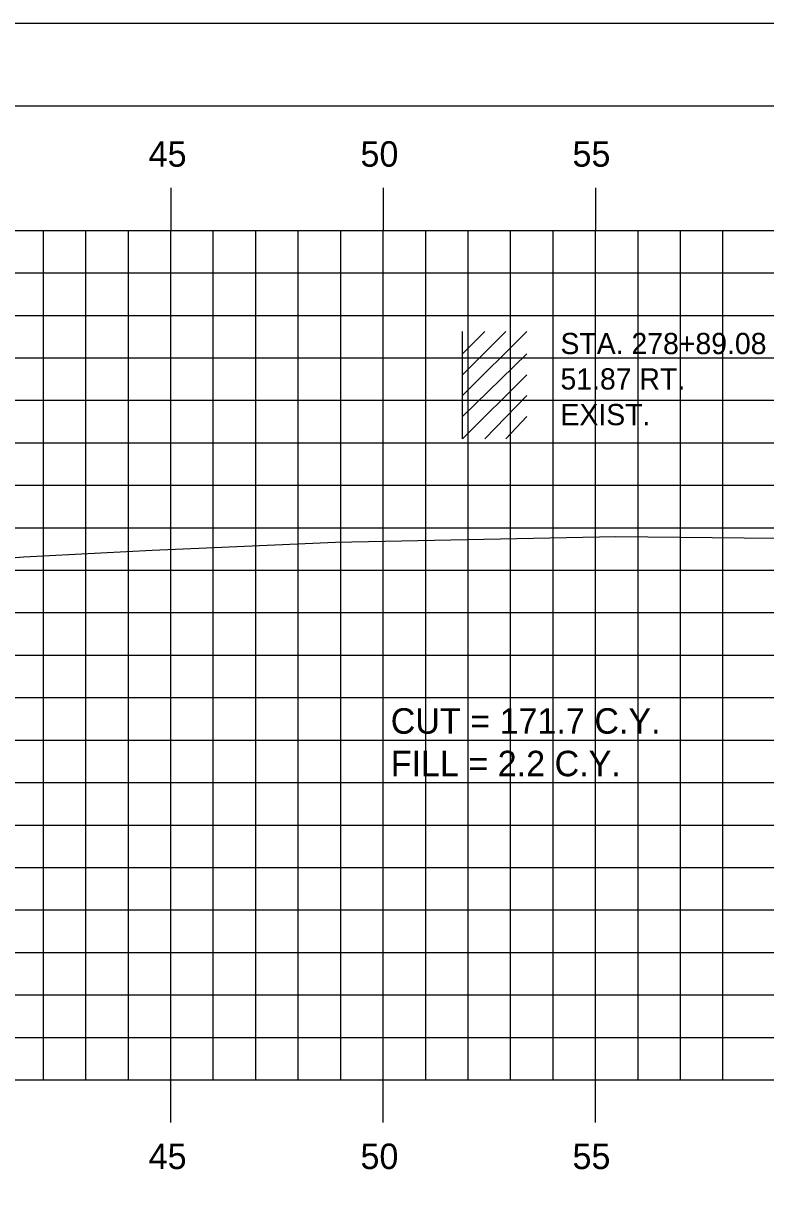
# Model space of a CAD drawing. Extents: x 854676 to 854846, y 366268 to 366378.
# Drawn here: x 854800.64 to 854818.1, y 366350.35 to 366378.18 of the extents above; entities that cross this region are included whole.
import ezdxf

# ---------------------------------------------------------------- set-up
doc = ezdxf.new("R2010")
doc.units = 0
for name, color, linetype in [('ANNOTATION', 7, 'Continuous'), ('BORDER', 7, 'Continuous'), ('D_Text_Monospaced', 7, 'Continuous'), ('H_V ANNOTATION', 7, 'Continuous'), ('MAJOR', 7, 'Continuous'), ('MINOR', 7, 'Continuous'), ('PLOT BOUNDARY', 7, 'Continuous'), ('S_Buildings_SillElevation', 7, 'Continuous'), ('S_Roadway_Centerline', 7, 'Continuous')]:
    doc.layers.add(name, color=color, linetype=linetype)

msp = doc.modelspace()

# ---------------------------------------------------------------- linework, layer by layer
at = {"layer": 'BORDER'}
msp.add_line((854844.107, 366376.236), (854684.107, 366376.236), dxfattribs=at)
at = {"layer": 'MAJOR'}
for p, q in [((854804.106, 366374.311), (854804.106, 366373.309)), ((854809.106, 366374.311), (854809.106, 366373.309)), ((854814.106, 366374.311), (854814.106, 366373.309)), ((854689.106, 366373.309), (854829.106, 366373.309)), ((854689.106, 366373.309), (854829.106, 366373.309)), ((854804.106, 366353.309), (854804.106, 366373.309)), ((854809.106, 366353.309), (854809.106, 366373.309)), ((854814.106, 366353.309), (854814.106, 366373.309)), ((854689.106, 366368.309), (854829.106, 366368.309)), ((854689.106, 366363.309), (854829.106, 366363.309)), ((854689.106, 366358.309), (854829.106, 366358.309)), ((854689.106, 366353.309), (854829.106, 366353.309)), ((854689.106, 366353.309), (854829.106, 366353.309)), ((854804.106, 366352.307), (854804.106, 366353.309)), ((854809.106, 366352.307), (854809.106, 366353.309)), ((854814.106, 366352.307), (854814.106, 366353.309))]:
    msp.add_line(p, q, dxfattribs=at)
at = {"layer": 'MINOR'}
for p, q in [((854801.106, 366353.309), (854801.106, 366373.309)), ((854802.106, 366353.309), (854802.106, 366373.309)), ((854803.106, 366353.309), (854803.106, 366373.309)), ((854805.106, 366353.309), (854805.106, 366373.309)), ((854806.106, 366353.309), (854806.106, 366373.309)), ((854807.106, 366353.309), (854807.106, 366373.309)), ((854808.106, 366353.309), (854808.106, 366373.309)), ((854810.106, 366353.309), (854810.106, 366373.309)), ((854811.106, 366353.309), (854811.106, 366373.309)), ((854812.106, 366353.309), (854812.106, 366373.309)), ((854813.106, 366353.309), (854813.106, 366373.309)), ((854815.106, 366353.309), (854815.106, 366373.309)), ((854816.106, 366353.309), (854816.106, 366373.309)), ((854817.106, 366353.309), (854817.106, 366373.309)), ((854689.106, 366372.309), (854829.106, 366372.309)), ((854689.106, 366371.309), (854829.106, 366371.309)), ((854689.106, 366370.309), (854829.106, 366370.309)), ((854689.106, 366369.309), (854829.106, 366369.309)), ((854689.106, 366367.309), (854829.106, 366367.309)), ((854689.106, 366366.309), (854829.106, 366366.309)), ((854689.106, 366365.309), (854829.106, 366365.309)), ((854689.106, 366364.309), (854829.106, 366364.309)), ((854689.106, 366362.309), (854829.106, 366362.309)), ((854689.106, 366361.309), (854829.106, 366361.309)), ((854689.106, 366360.309), (854829.106, 366360.309)), ((854689.106, 366359.309), (854829.106, 366359.309)), ((854689.106, 366357.309), (854829.106, 366357.309)), ((854689.106, 366356.309), (854829.106, 366356.309)), ((854689.106, 366355.309), (854829.106, 366355.309)), ((854689.106, 366354.309), (854829.106, 366354.309))]:
    msp.add_line(p, q, dxfattribs=at)
at = {"layer": 'PLOT BOUNDARY'}
msp.add_lwpolyline([(854676.013, 366268.177), (854846.013, 366268.177), (854846.013, 366378.177), (854676.013, 366378.177)], close=True, dxfattribs=at)
at = {"layer": 'S_Buildings_SillElevation'}
for p, q in [((854810.976, 366368.402), (854810.976, 366370.928)), ((854810.976, 366369.419), (854812.485, 366370.928)), ((854810.976, 366369.911), (854811.993, 366370.928)), ((854810.976, 366370.403), (854811.501, 366370.928)), ((854810.976, 366368.927), (854812.485, 366370.403)), ((854810.976, 366368.402), (854812.485, 366369.911)), ((854811.501, 366368.402), (854812.485, 366369.419)), ((854811.993, 366368.402), (854812.485, 366368.927))]:
    msp.add_line(p, q, dxfattribs=at)
at = {"layer": 'S_Roadway_Centerline'}
msp.add_lwpolyline([(854760.071, 366365.226), (854771.088, 366364.995), (854777.534, 366364.686), (854778.369, 366364.622), (854778.629, 366364.634), (854779.762, 366364.729), (854780.446, 366364.709), (854781.576, 366364.775), (854785.006, 366365.003), (854787.636, 366365.067), (854790.678, 366365.23), (854793.359, 366365.326), (854798.518, 366365.484), (854799.286, 366365.525), (854800.647, 366365.62), (854803.663, 366365.778), (854804.946, 366365.832), (854807.983, 366365.97), (854814.583, 366366.102), (854822.139, 366366.02), (854822.216, 366366.887)], dxfattribs=at)

# ---------------------------------------------------------------- texts
at = {"layer": 'ANNOTATION'}
for s, p in [('CUT = 171.7 C.Y.', (854809.283, 366361.459)), ('FILL = 2.2 C.Y.', (854809.283, 366360.457))]:
    msp.add_text(s, height=0.6, dxfattribs=at).set_placement(p)
at = {"layer": 'D_Text_Monospaced'}
for s, height, p in [('STA. 278+89.08', 0.49998, (854813.28, 366370.396)), ('51.87 RT.', 0.5, (854813.28, 366369.562)), ('EXIST. ', 0.5, (854813.28, 366368.722))]:
    msp.add_text(s, height=height, dxfattribs=at).set_placement(p)
at = {"layer": 'H_V ANNOTATION'}
for s, p in [('45', (854803.584, 366374.809)), ('50', (854808.571, 366374.809)), ('55', (854813.563, 366374.809)), ('45', (854803.584, 366351.209)), ('50', (854808.571, 366351.209)), ('55', (854813.563, 366351.209))]:
    msp.add_text(s, height=0.6, dxfattribs=at).set_placement(p)

doc.saveas('drawing.dxf')
